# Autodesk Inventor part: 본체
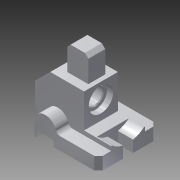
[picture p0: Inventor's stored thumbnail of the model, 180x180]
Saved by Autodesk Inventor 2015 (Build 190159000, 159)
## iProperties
Created: 2016-11
Part Number: 본체
Material: 알루미늄 6061
Document SubType Name: Modeling
Designer: LineLG02
Mass: 487.148 g
Surface Area: 258.421 cm^2
Volume: 180.425 cm^3
Density: 2.7 g/cm^3
Appearance: 알루미늄 - 평지
Author: LineLG02
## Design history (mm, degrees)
sketch "스케치1"
  geometry: L1 (-38, 35)-(33, 35); L2 (38, 30)-(38, -30); L3 (33, -35)-(-38, -35); L4 (-38, -35)-(-38, 35); L5 (-38, 35)-(38, -35); L6 (38, 35)-(-38, -35); L7 (33, 35)-(38, 30); L8 (38, -30)-(33, -35); 1 further point
  constraints: 16 end point, 4 point on line, 2 midpoint, 2 parallel, 1 horizontal, 1 perpendicular
  dimensions: "d0" = 76 distance of L5.end L3.end; "d1" = 70 distance of L6.start L5.end; "d2" = 5 distance of L1.end L6.start; "d3" = 5 distance of L2.start L6.start (= d2); "d4" = 5 distance of L2.end L5.end (= d2); "d5" = 5 distance of L3.start L5.end (= d4)
extrude "돌출1" new body sketch "스케치1" distance "d6" = 15; taper "d7" = 0 deg
sketch "스케치2"
  geometry: L1 (-52, 20)-(6, 20); L2 (-52, -20)-(6, -20); L3 (-52, -20)-(-52, 20); L4 (6, -20)-(6, 20); L5 (-38, -35)-(33, -35) reference; L6 (-38, 35)-(-38, -35) reference; 1 further point
  constraints: 8 end point, 1 horizontal, 1 parallel, 1 vertical
  dimensions: "d11" = 58 distance between parallel lines of L3 L4; "d12" = 15 distance between parallel lines of L2 L5; "d13" = 55 distance between parallel lines of L1 L5; "d14" = 44 distance between parallel lines of L6 L4
extrude "돌출2" join sketch "스케치2" distance "d15" = 45; taper "d16" = 0 deg
sketch "스케치3"
  geometry: L1 (76, 0)-(71, 0) reference; L2 (23, 0)-(23, 7); L3 (3, 0)-(3, 7); L4 (23, 0)-(3, 0); L5 (3, 7)-(23, 7); L6 (0, 0)-(0, 15) reference; L7 (71, 0)-(0, 0) reference; L8 (-14, 60)-(44, 60) reference; L9 (76, 0)-(76, 15) reference; 1 further point
  constraints: 8 end point, 2 horizontal
  dimensions: "d21" = 3 distance between parallel lines of L6 L3; "d23" = 7 distance between parallel lines of L4 L5; "d24" = 53 distance between parallel lines of L8 L5; "d26" = 53 distance between parallel lines of L9 L2
extrude "돌출3" cut sketch "스케치3" distance "d27" = 200; taper "d28" = 0 deg
sketch "스케치4"
  geometry: L1 (6, 20)-(6, -20) reference; L2 (6, -20)-(6, 20); L3 (-38, -20)-(-38, -35) reference; L4 (38, 30)-(38, -30) reference; L5 (6, -20)-(38, -20); L6 (38, -20)-(38, 20); L7 (38, 20)-(6, 20); 1 further point
  constraints: 8 end point, 2 point on line, 1 collinear
  dimensions: "d29" = 32 distance of L1.end L5.end; "d30" = 40 distance of L5.end L6.end
extrude "돌출4" join sketch "스케치4" distance "d31" = 5; taper "d32" = 0 deg
sketch "스케치5"
  geometry: L1 (52, 60)-(52, 15) reference; L2 (52, 15)-(38, 15) reference; L3 (38, 15)-(38, 0) reference; L4 (38, 0)-(35, 0) reference; L5 (35, 0)-(35, 7) reference; L6 (35, 7)-(15, 7) reference; L7 (15, 7)-(15, 0) reference; L8 (15, 0)-(-38, 0) reference; L9 (-38, 0)-(-38, 20) reference; L10 (-38, 20)-(-6, 20) reference; L11 (-6, 20)-(-6, 60) reference; L12 (-6, 60)-(52, 60) reference; L13 (52, 15)-(52, 12); L14 (52, 12)-(38, 12); 1 further point
  constraints: 4 end point, 2 point on line, 1 perpendicular, 1 vertical
  dimensions: "d33" = 48 distance of L1.start L13.end; "d34" = 14 distance between parallel lines of L3 L13
extrude "돌출5" join sketch "스케치5" stored distance "d35" = 40; taper "d36" = 0 deg
chamfer "모따기1" distance "d37" = 4; stored, may be unused: second distance "d38" = 2, angle "d39" = 45 deg
sketch "스케치6"
  geometry: L1 (-10, -3)-(-14, 1) reference; L2 (-10, -3)-(0, -3) reference; L3 (0, 0)-(0, -3) reference; L4 (76, 0)-(0, 0) reference; L5 (76, 0)-(76, 5) reference; L6 (44, 5)-(76, 5) reference; L7 (44, 5)-(44, 45) reference; L8 (-14, 45)-(44, 45) reference; L9 (-14, 45)-(-14, 1) reference; L10 (-14, 45)-(-14, 1) reference; L11 (-14, 27)-(4, 45); 1 further point
  constraints: 2 end point, 2 point on line
  dimensions: "d44" = 45 deg angle of L9 L11; "d45" = 30 vertical distance of L11.start L1.start
extrude "돌출6" cut sketch "스케치6" distance "d46" = 40; taper "d47" = 0 deg
sketch "스케치7"
  geometry: L1 (-34, -20)-(-34, 20) reference; L2 (-34, 20)-(6, 20) reference; L3 (6, 20)-(6, -20) reference; L4 (6, -20)-(-34, -20) reference; L5 (1, 10)-(-24, 10); L6 (1, -10)-(-24, -10); L7 (-24, -10)-(-24, 10); L8 (1, -10)-(1, 10); 1 further point
  constraints: 8 end point, 2 vertical
  dimensions: "d52" = 5 distance between parallel lines of L3 L8; "d53" = 10 distance between parallel lines of L2 L5; "d54" = 10 distance between parallel lines of L1 L7; "d55" = 10 distance between parallel lines of L4 L6
extrude "돌출7" join sketch "스케치7" distance "d56" = 30; taper "d57" = 0 deg
node "스케치8"
sketch "스케치9"
  geometry: L1 (26, 0)-(26, 40) reference; L2 (0, 40)-(26, 40) reference; L3 (0, 0)-(0, 40) reference; L4 (26, 0)-(0, 0) reference; L5 (26, 0)-(26, 40) reference; C1 r 10 at (26, 20); 1 further point
  constraints: 1 centre point, 1 midpoint
  dimensions: "d58" = 20 diameter of C1
extrude "돌출8" cut sketch "스케치9" distance "d59" = 200; taper "d60" = 0 deg
sketch "스케치10"
  geometry: L1 (40, 0)-(40, 40) reference; L2 (40, 40)-(0, 40) reference; L3 (0, 0)-(0, 40) reference; L4 (40, 0)-(0, 0) reference; C1 r 10 at (18, 20) reference; C2 r 14.5 at (18, 20); 1 further point
  constraints: 1 centre point, 1 coincident
  dimensions: "d61" = 29 diameter of C2
extrude "돌출9" cut sketch "스케치10" distance "d62" = 7; taper "d63" = 0 deg
chamfer "모따기2" distance "d64" = 1; stored, may be unused: second distance "d65" = 2, angle "d66" = 45 deg
chamfer "모따기3" distance "d67" = 4; stored, may be unused: second distance "d68" = 2, angle "d69" = 45 deg
sketch "스케치11"
  geometry: L1 (23, -15)-(23, -8) reference; L2 (23, -8)-(3, -8) reference; L3 (3, -8)-(3, -15) reference; L4 (3, -15)-(0, -15) reference; L5 (0, -15)-(0, 0) reference; L6 (0, 0)-(71, 0) reference; L7 (71, 0)-(71, -15) reference; L8 (71, -15)-(23, -15) reference; A1 r 13 centre (13, 0) between (26, 0) and (0, 0); 1 further point
  constraints: 2 point on circle, 1 centre point, 1 end point, 1 point on line
  dimensions: "d71" = 13 radius of A1; "d72" = 8 vertical distance of L1.end A1.centre
extrude "돌출10" join sketch "스케치11" distance "d73" = 70; taper "d74" = 0 deg
fillet "모깎기1" dims "d75" = 5
sketch "스케치12"
  geometry: L1 (0, 60)-(0, 0) reference; L2 (0, 0)-(-15, 0) reference; L3 (-15, 0)-(-15, 10) reference; L4 (-15, 10)-(-20, 10) reference; L5 (-20, 10)-(-20, 50) reference; L6 (-20, 50)-(-15, 50) reference; L7 (-15, 50)-(-15, 60) reference; L8 (-15, 60)-(0, 60) reference; C1 r 11 at (-42, 30) reference; A1 r 29 centre (-42, 30) between (-20, 11.106) and (-20, 48.894); 1 further point
  constraints: 2 point on circle, 2 point on line, 1 centre point, 1 coincident
  dimensions: "d76" = 29 radius of A1
extrude "돌출11" cut sketch "스케치12" distance "d77" = 18; taper "d78" = 0 deg
sketch "스케치13"
  geometry: L1 (15, -35)-(15, 35) reference; L2 (15, 35)-(-33, 35) reference; L3 (-33, 35)-(-38, 30) reference; L4 (-38, 30)-(-38, -30) reference; L5 (-38, -30)-(-33, -35) reference; L6 (-33, -35)-(15, -35) reference; L7 (-38, 6)-(-20, 6); L8 (-38, -6)-(-20, -6); L9 (-20, -6)-(-20, 6); L10 (-38, -6)-(-38, 6); L11 (-38, -18.894)-(-38, 18.894) reference; 1 further point
  constraints: 8 end point, 1 collinear, 1 vertical
  dimensions: "d82" = 12 distance between parallel lines of L7 L8; "d83" = 18 distance between parallel lines of L4 L9; "d84" = 38 horizontal distance of L7.start point (0, 0); "d85" = 6 distance from line of point (0, 0) L8; "d86" = 6 vertical distance of point (0, 0) L7.end
extrude "돌출12" cut sketch "스케치13" distance "d87" = 18; taper "d88" = 0 deg
node "솔리드1"
node "투영된 루프1"
node "투영된 루프2"
node "투영된 루프3"
node "투영된 루프4"
node "절단 모서리 투영1"
node "절단 모서리 투영2"
node "절단 모서리 투영3"
node "절단 모서리 투영4"
other parameters: "d70" = 13
